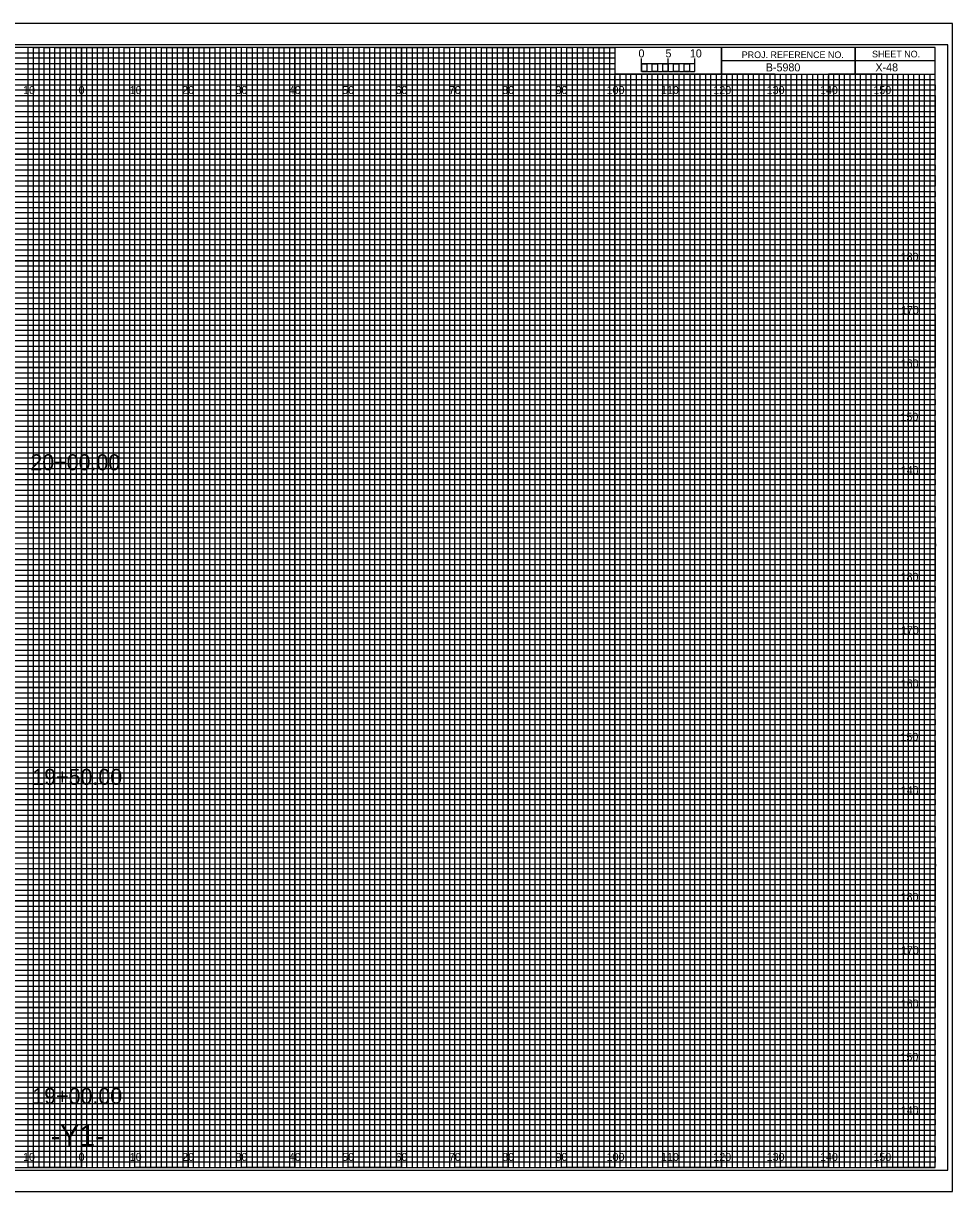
# Model space of a CAD drawing. Extents: x -13 to 323, y -5 to 4834.
# Drawn here: x 149.1 to 323.3, y 435.5 to 654.5 of the extents above; entities that cross this region are included whole.
import ezdxf

# ---------------------------------------------------------------- set-up
doc = ezdxf.new("R2010")
doc.units = 0
for name, color, linetype in [('Exist CMT Pavement', 7, 'Continuous'), ('Exist Cross Section Cell', 7, 'Continuous'), ('Exist XS Center Line Elevation Label', 7, 'Continuous'), ('Exist XS Ground Line', 7, 'Continuous'), ('Prop CMT Pvmt Course 1', 7, 'Continuous'), ('Prop CMT Pvmt Course 1 Wedge', 7, 'Continuous'), ('Prop CMT Pvmt Course 2', 7, 'Continuous'), ('Prop CMT Pvmt Course 2 Wedge', 7, 'Continuous'), ('Prop CMT Pvmt Course 3', 7, 'Continuous'), ('Prop CMT Pvmt Course 3 Wedge', 7, 'Continuous'), ('Prop CMT Pvmt Surface', 7, 'Continuous'), ('Prop CMT Pvmt Surface Shoulder', 7, 'Continuous'), ('Prop CMT Shld Paved Course 1', 7, 'Continuous'), ('Prop CMT Shld Paved Course 2', 7, 'Continuous'), ('Prop CMT Shld Paved Course 3', 7, 'Continuous'), ('Prop CMT Slope Grass', 7, 'Continuous'), ('Prop CMT Subgrade Earthwork', 7, 'Continuous')]:
    doc.layers.add(name, color=color, linetype=linetype)

msp = doc.modelspace()

# ---------------------------------------------------------------- linework, layer by layer
at = {"layer": 'Exist XS Center Line Elevation Label'}
for points in [[(145, 440), (155, 440), (155, 650), (165, 650), (165, 440), (175, 440), (175, 650), (185, 650), (185, 440), (195, 440), (195, 650), (205, 650), (205, 440), (215, 440), (215, 650), (225, 650), (225, 440), (235, 440), (235, 650), (245, 650), (245, 440), (255, 440), (255, 650), (259.93, 650), (260, 650), (260, 645), (264.99, 645), (264.99, 440), (275, 440), (275, 645), (285, 645), (285, 440), (295, 440), (295, 645), (305, 645), (305, 440), (315, 440), (315, 645)], [(0, 645), (275, 645)], [(0, 625), (320, 625), (320, 635), (0, 635)], [(0, 605), (320, 605), (320, 615), (0, 615)], [(0, 585), (320, 585), (320, 595), (0, 595)], [(0, 565), (320, 565), (320, 575), (0, 575)], [(0, 545), (320, 545), (320, 555), (0, 555)], [(0, 525), (320, 525), (320, 535), (0, 535)], [(0, 505), (320, 505), (320, 515), (0, 515)], [(0, 485), (320, 485), (320, 495), (0, 495)], [(0, 465), (320, 465), (320, 475), (0, 475)], [(0, 445), (320, 445), (320, 455), (0, 455)]]:
    msp.add_lwpolyline(points, dxfattribs=at)
at = {"layer": 'Exist XS Ground Line'}
for p, q in [((150, 650), (140, 650)), ((150, 440), (150, 650)), ((170, 650), (160, 650)), ((160, 650), (160, 440)), ((170, 440), (170, 650)), ((190, 650), (180, 650)), ((180, 650), (180, 440)), ((190, 440), (190, 650)), ((210, 650), (200, 650)), ((200, 650), (200, 440)), ((210, 440), (210, 650)), ((230, 650), (220, 650)), ((220, 650), (220, 440)), ((230, 440), (230, 650)), ((250, 650), (240, 650)), ((240, 650), (240, 440)), ((250, 440), (250, 650)), ((260, 650), (260, 440)), ((270, 440), (270, 645)), ((290, 645), (280, 645)), ((280, 645), (280, 440)), ((290, 440), (290, 645)), ((310, 645), (300, 645)), ((300, 645), (300, 440)), ((310, 440), (310, 645)), ((160, 440), (150, 440)), ((180, 440), (170, 440)), ((200, 440), (190, 440)), ((220, 440), (210, 440)), ((240, 440), (230, 440)), ((260, 440), (250, 440)), ((280, 440), (270, 440)), ((300, 440), (290, 440)), ((320, 440), (310, 440)), ((320, 440), (320, 440))]:
    msp.add_line(p, q, dxfattribs=at)
for points in [[(0, 640), (320, 640), (320, 630), (0, 630)], [(0, 620), (320, 620), (320, 610), (0, 610)], [(0, 600), (320, 600), (320, 590), (0, 590)], [(0, 580), (320, 580), (320, 570), (0, 570)], [(0, 560), (320, 560), (320, 550), (0, 550)], [(0, 540), (320, 540), (320, 530), (0, 530)], [(0, 520), (320, 520), (320, 510), (0, 510)], [(0, 500), (320, 500), (320, 490), (0, 490)], [(0, 480), (320, 480), (320, 470), (0, 470)], [(0, 460), (320, 460), (320, 450), (0, 450)]]:
    msp.add_lwpolyline(points, dxfattribs=at)
at = {"layer": 'Prop CMT Pvmt Course 1'}
for p, q in [((267, 645), (266.01, 645)), ((266.01, 645), (266.01, 440)), ((267, 440), (267, 645)), ((269, 645), (268, 645)), ((268, 645), (268, 440)), ((269, 440), (269, 645)), ((266.01, 440), (265, 440)), ((268, 440), (267, 440))]:
    msp.add_line(p, q, dxfattribs=at)
for points in [[(150, 440), (151, 440), (151, 650), (152, 650), (152, 440)], [(152, 440), (153, 440), (153, 650), (154, 650), (154, 440)], [(155, 440), (156, 440), (156, 650), (157, 650), (157, 440)], [(157, 440), (158, 440), (158, 650), (159, 650), (159, 440)], [(160, 440), (161, 440), (161, 650), (162, 650), (162, 440)], [(162, 440), (163, 440), (163, 650), (164, 650), (164, 440)], [(165, 440), (166, 440), (166, 650), (167, 650), (167, 440)], [(167, 440), (168, 440), (168, 650), (169, 650), (169, 440)], [(170, 440), (171, 440), (171, 650), (172, 650), (172, 440)], [(172, 440), (173, 440), (173, 650), (174, 650), (174, 440)], [(175, 440), (176, 440), (176, 650), (177, 650), (177, 440)], [(177, 440), (178, 440), (178, 650), (179, 650), (179, 440)], [(180, 440), (181, 440), (181, 650), (182, 650), (182, 440)], [(182, 440), (183, 440), (183, 650), (184, 650), (184, 440)], [(185, 440), (186, 440), (186, 650), (187, 650), (187, 440)], [(187, 440), (188, 440), (188, 650), (189, 650), (189, 440)], [(190, 440), (191, 440), (191, 650), (192, 650), (192, 440)], [(192, 440), (193, 440), (193, 650), (194, 650), (194, 440)], [(195, 440), (196, 440), (196, 650), (197, 650), (197, 440)], [(197, 440), (198, 440), (198, 650), (199, 650), (199, 440)], [(200, 440), (201, 440), (201, 650), (202, 650), (202, 440)], [(202, 440), (203, 440), (203, 650), (204, 650), (204, 440)], [(205, 440), (206, 440), (206, 650), (207, 650), (207, 440)], [(207, 440), (208, 440), (208, 650), (209, 650), (209, 440)], [(210, 440), (211, 440), (211, 650), (212, 650), (212, 440)], [(212, 440), (213, 440), (213, 650), (214, 650), (214, 440)], [(215, 440), (216, 440), (216, 650), (217, 650), (217, 440)], [(217, 440), (218, 440), (218, 650), (219, 650), (219, 440)], [(220, 440), (221, 440), (221, 650), (222, 650), (222, 440)], [(222, 440), (223, 440), (223, 650), (224, 650), (224, 440)], [(225, 440), (226, 440), (226, 650), (227, 650), (227, 440)], [(227, 440), (228, 440), (228, 650), (229, 650), (229, 440)], [(230, 440), (231, 440), (231, 650), (232, 650), (232, 440)], [(232, 440), (233, 440), (233, 650), (234, 650), (234, 440)], [(235, 440), (236, 440), (236, 650), (237, 650), (237, 440)], [(237, 440), (238, 440), (238, 650), (239, 650), (239, 440)], [(240, 440), (241, 440), (241, 650), (242, 650), (242, 440)], [(242, 440), (243, 440), (243, 650), (244, 650), (244, 440)], [(245, 440), (246, 440), (246, 650), (247, 650), (247, 440)], [(247, 440), (248, 440), (248, 650), (249, 650), (249, 440)], [(250, 440), (251, 440), (251, 650), (252, 650), (252, 440)], [(252, 440), (253, 440), (253, 650), (254, 650), (254, 440)], [(255, 440), (256, 440), (256, 650), (257, 650), (257, 440)], [(257, 440), (258, 440), (258, 650), (259, 650), (259, 440)], [(260, 440), (261, 440), (261, 645), (262.02, 645), (262.02, 440)], [(262, 440), (263, 440), (263, 645), (263.99, 645), (263.99, 440)], [(270, 440), (270.98, 440), (270.98, 645), (272, 645), (272, 440)], [(272, 440), (273, 440), (273, 645), (274.05, 645), (274.05, 440)], [(275, 440), (276, 440), (276, 645), (277, 645), (277, 440)], [(277, 440), (278, 440), (278, 645), (279, 645), (279, 440)], [(280, 440), (281, 440), (281, 645), (282, 645), (282, 440)], [(282, 440), (283, 440), (283, 645), (284, 645), (284, 440)], [(285, 440), (286, 440), (286, 645), (287, 645), (287, 440)], [(287, 440), (288, 440), (288, 645), (289, 645), (289, 440)], [(290, 440), (291, 440), (291, 645), (292, 645), (292, 440)], [(292, 440), (293, 440), (293, 645), (294, 645), (294, 440)], [(295, 440), (296, 440), (296, 645), (297, 645), (297, 440)], [(297, 440), (298, 440), (298, 645), (299, 645), (299, 440)], [(300, 440), (301, 440), (301, 645), (302, 645), (302, 440)], [(302, 440), (303, 440), (303, 645), (304, 645), (304, 440)], [(305, 440), (306, 440), (306, 645), (307, 645), (307, 440)], [(307, 440), (308, 440), (308, 645), (309, 645), (309, 440)], [(310, 440), (311, 440), (311, 645), (312, 645), (312, 440)], [(312, 440), (313, 440), (313, 645), (314, 645), (314, 440)], [(315, 440), (316, 440), (316, 645), (317, 645), (317, 440)], [(317, 440), (318, 440), (318, 645), (319, 645), (319, 440)]]:
    msp.add_lwpolyline(points, dxfattribs=at)
at = {"layer": 'Prop CMT Pvmt Course 2'}
for p, q in [((323.3, 654.5), (-13.4, 654.5)), ((-13.4, 435.5), (323.3, 435.5))]:
    msp.add_line(p, q, dxfattribs=at)
at = {"layer": 'Prop CMT Pvmt Surface Shoulder'}
for p, q in [((305, 650), (305, 645)), ((305, 645), (305, 650)), ((280, 647.5), (280, 645)), ((320, 647.49), (280, 647.49)), ((280, 645), (320, 645))]:
    msp.add_line(p, q, dxfattribs=at)
for points in [[(320, 650), (0, 650), (0, 440), (320, 440)], [(280, 650), (260, 650), (260, 645.03), (280, 645.03)], [(320, 650), (280, 650), (280, 645), (320, 645)]]:
    msp.add_lwpolyline(points, close=True, dxfattribs=at)
at = {"layer": 'Prop CMT Shld Paved Course 1'}
msp.add_lwpolyline([(-13.4, 435.5), (323.3, 435.5), (323.3, 654.5), (-13.4, 654.5)], close=True, dxfattribs=at)
at = {"layer": 'Prop CMT Shld Paved Course 2'}
msp.add_lwpolyline([(-10.8, 439.5), (322.4, 439.5), (322.4, 650.5), (-10.8, 650.5)], close=True, dxfattribs=at)
at = {"layer": 'Prop CMT Shld Paved Course 3'}
for p, q in [((150, 440), (150, 650)), ((160, 440), (160, 650)), ((170, 440), (170, 650)), ((180, 440), (180, 650)), ((190, 440), (190, 650)), ((200, 440), (200, 650)), ((210, 440), (210, 650)), ((220, 440), (220, 650)), ((230, 440), (230, 650)), ((240, 440), (240, 650)), ((250, 440), (250, 650)), ((260, 440), (260, 644.69)), ((270, 440), (270, 644.69)), ((280, 440), (280, 644.69)), ((290, 440), (290, 644.69)), ((300, 440), (300, 644.69)), ((310, 440), (310, 644.69)), ((0, 640), (320, 640)), ((0, 630), (320, 630)), ((0, 620), (320, 620)), ((0, 610), (320, 610)), ((0, 600), (320, 600)), ((0, 590), (320, 590)), ((0, 580), (320, 580)), ((0, 570), (320, 570)), ((0, 560), (320, 560)), ((0, 550), (320, 550)), ((0, 540), (320, 540)), ((0, 530), (320, 530)), ((0, 520), (320, 520)), ((0, 510), (320, 510)), ((0, 500), (320, 500)), ((0, 490), (320, 490)), ((0, 480), (320, 480)), ((0, 470), (320, 470)), ((0, 460), (320, 460)), ((0, 450), (320, 450))]:
    msp.add_line(p, q, dxfattribs=at)
at = {"layer": 'Prop CMT Slope Grass'}
for p, q in [((0, 649), (260, 649)), ((260, 649), (260, 647.98)), ((260, 647.98), (0, 647.98)), ((0, 647), (260, 647)), ((260, 647), (260, 645.89)), ((260, 645.89), (0, 645.89)), ((0, 644), (320, 644))]:
    msp.add_line(p, q, dxfattribs=at)
for points in [[(0, 643), (270, 643), (320, 643), (320, 642), (0, 642)], [(0, 641), (320, 641), (320, 639), (0, 639)], [(0, 638), (320, 638), (320, 637), (0, 636.98)], [(0, 636), (320, 636), (320, 634), (0, 634)], [(0, 633), (320, 633), (320, 632), (0, 632)], [(0, 631), (320, 631), (320, 629), (0, 629)], [(0, 628), (320, 628), (320, 627), (0, 627)], [(0, 626), (320, 626), (320, 624), (0, 624)], [(0, 623), (320, 623), (320, 622), (0, 622)], [(0, 621), (320, 621), (320, 619), (0, 619)], [(0, 618), (320, 618), (320, 617), (0, 617)], [(0, 616), (320, 616), (320, 613.95), (320, 613), (320, 612), (0, 612)], [(0, 614), (320, 614), (320, 613), (0, 613)], [(0, 611), (320, 611), (320, 609), (0, 609.03)], [(0, 609.03), (320, 609), (320, 608), (0, 608)], [(0, 607), (320, 607), (320, 606), (0, 606)], [(0, 604), (320, 604), (320, 603), (0, 603)], [(0, 602), (320, 602), (320, 601), (0, 601)], [(-0.07, 598.89), (320, 598.89), (320, 597.88), (-0.07, 597.88)], [(0, 597), (320, 597), (320, 596), (0, 596)], [(0, 594), (320, 594), (320, 593), (0, 593)], [(0, 592), (320, 592), (320, 591), (0, 591)], [(0, 589), (320, 589), (320, 588), (0, 588)], [(0, 587), (320, 587), (320, 586), (0, 586)], [(0, 584), (320, 584), (320, 583), (0, 583)], [(0, 582), (320, 582), (320, 581), (0, 581)], [(0, 579), (320, 579), (319.99, 577.98), (0, 578)], [(0, 577), (320, 577), (320, 576), (0, 576)], [(0, 574), (320, 574), (320, 573), (0, 573)], [(0, 572), (320, 572), (320, 571), (0, 571)], [(0, 569), (320, 569), (320, 568), (0, 568)], [(0, 567), (320, 567), (320, 566), (0, 566)], [(0, 564), (320, 564), (320, 563), (0, 563)], [(0, 562), (320, 562), (320, 561), (0, 561)], [(0, 559), (320, 559), (320, 558), (0, 558)], [(0, 556.99), (320.07, 556.91), (320, 556), (0, 556)], [(0, 554), (320, 554), (320, 553), (0, 553)], [(0, 552), (320, 552), (320, 551), (0, 551)], [(0, 549), (320, 549), (320, 548), (0, 548)], [(0, 547), (320, 547), (320, 546), (0, 546)], [(0, 544), (320, 544), (320, 543), (0, 543)], [(0, 542), (320, 542), (320, 541), (0, 541)], [(0, 539), (320, 539), (320, 538), (0, 538)], [(0, 537), (320, 537), (320, 536), (0, 536)], [(0, 534), (320, 534), (320, 533), (0, 533)], [(0, 532), (320, 532), (320, 531), (0, 531)], [(0, 529), (320, 529), (320, 528), (0, 528)], [(0, 527), (320, 527), (320, 526), (0, 526)], [(0, 524), (320, 524), (320, 523), (0, 523)], [(0, 522), (320, 522), (320, 521), (0, 521)], [(0, 519), (320, 519), (319.99, 517.98), (0, 518)], [(0, 517), (320, 517), (320, 516), (0, 516)], [(0, 514), (320, 514), (320, 513), (0, 513)], [(0, 512), (320, 512), (320, 511), (0, 511)], [(0, 509), (320, 509), (320, 508), (0, 508)], [(0, 507), (320, 507), (320, 506), (0, 506)], [(0, 504), (320, 504), (320, 503), (0, 503)], [(0, 502), (320, 502), (320, 501), (0, 501)], [(0, 499), (320, 499), (320, 498), (0, 498)], [(0, 496.99), (320.07, 496.91), (320, 496), (0, 496)], [(0, 494), (320, 494), (320, 493), (0, 493)], [(0, 492), (320, 492), (320, 491), (0, 491)], [(0, 489), (320, 489), (320, 488), (0, 488)], [(0, 487), (320, 487), (320, 486), (0, 486)], [(0, 484), (320, 484), (320, 483), (0, 483)], [(0, 482), (320, 482), (320, 481), (0, 481)], [(0, 479), (320, 479), (320, 478), (0, 478)], [(0, 477), (320, 477), (320, 476), (0, 476)], [(0, 474), (320, 474), (320, 473), (0, 473)], [(0, 472), (320, 472), (320, 471), (0, 471)], [(0, 469), (320, 469), (320, 468), (0, 468)], [(0, 467), (320, 467), (320, 466), (0, 466)], [(0, 464), (320, 464), (320, 463), (0, 463)], [(0, 462), (320, 462), (320, 461), (0, 461)], [(0, 459), (320, 459), (320, 458), (0, 458)], [(0, 457), (320, 457), (320, 456), (0, 456)], [(0, 454), (320, 454), (320, 453), (0, 453)], [(0, 452), (320, 452), (320, 451), (0, 451)], [(0, 449), (320, 449), (320, 448), (0, 448)], [(0, 447), (320, 447), (320, 446), (0, 446)], [(0, 444), (320, 444), (320, 443), (0, 443)], [(0, 442), (320, 442), (320, 441), (0, 441)]]:
    msp.add_lwpolyline(points, dxfattribs=at)
at = {"layer": 'Prop CMT Subgrade Earthwork'}
for p, q in [((265, 645.49), (265, 647.9)), ((265, 646.9), (265, 647.9)), ((270, 645.49), (270, 647.9)), ((275, 645.49), (275, 647.9)), ((275, 646.9), (275, 647.9))]:
    msp.add_line(p, q, dxfattribs=at)
for points in [[(275, 646.9), (265, 646.9), (265, 645.49), (275, 645.49)], [(265, 646.9), (266, 646.9), (266, 645.49), (265, 645.49)], [(267, 646.9), (268, 646.9), (268, 645.49), (267, 645.49)], [(269, 646.9), (270, 646.9), (270, 645.49), (269, 645.49)], [(271, 646.9), (272, 646.9), (272, 645.49), (271, 645.49)], [(273, 646.9), (274, 646.9), (274, 645.49), (273, 645.49)]]:
    msp.add_lwpolyline(points, close=True, dxfattribs=at)

# ---------------------------------------------------------------- texts
at = {"layer": 'Exist CMT Pavement'}
msp.add_text('-Y1-', height=4, dxfattribs=at).set_placement((154.21, 444))
at = {"layer": 'Exist Cross Section Cell'}
for s, p in [('10', (149.04, 641.25)), ('0', (159.45, 641.25)), ('0', (159.45, 641.25)), ('10', (169.04, 641.25)), ('20', (178.86, 641.25)), ('30', (188.86, 641.25)), ('40', (198.86, 641.25)), ('50', (208.86, 641.25)), ('60', (218.86, 641.25)), ('70', (228.86, 641.25)), ('80', (238.86, 641.25)), ('90', (248.86, 641.25)), ('100', (258.44, 641.25)), ('110', (268.62, 641.25)), ('120', (278.44, 641.25)), ('130', (288.44, 641.25)), ('140', (298.44, 641.25)), ('150', (308.44, 641.25)), ('10', (149.04, 441.25)), ('0', (159.45, 441.25)), ('0', (159.45, 441.25)), ('10', (169.04, 441.25)), ('20', (178.86, 441.25)), ('30', (188.86, 441.25)), ('40', (198.86, 441.25)), ('50', (208.86, 441.25)), ('60', (218.86, 441.25)), ('70', (228.86, 441.25)), ('80', (238.86, 441.25)), ('90', (248.86, 441.25)), ('100', (258.44, 441.25)), ('110', (268.62, 441.25)), ('120', (278.44, 441.25)), ('130', (288.44, 441.25)), ('140', (298.44, 441.25)), ('150', (308.44, 441.25))]:
    msp.add_text(s, height=1.5, dxfattribs=at).set_placement(p)
at = {"layer": 'Prop CMT Pvmt Course 1 Wedge'}
for s, p in [('20+00.00', (150.41, 570.72)), ('19+50.00', (150.77, 511.75)), ('19+00.00', (150.77, 451.94))]:
    msp.add_text(s, height=3, dxfattribs=at).set_placement(p)
at = {"layer": 'Prop CMT Pvmt Course 2 Wedge'}
msp.add_text('X-48', height=1.5, dxfattribs=at).set_placement((308.83, 645.5))
at = {"layer": 'Prop CMT Pvmt Course 3'}
for s, p in [('180', (313.55, 610)), ('170', (313.61, 600)), ('160', (313.57, 590)), ('150', (313.52, 580)), ('140', (313.57, 570)), ('180', (313.55, 550)), ('170', (313.61, 540)), ('160', (313.57, 530)), ('150', (313.52, 520)), ('140', (313.57, 510)), ('180', (313.55, 490)), ('170', (313.61, 480)), ('160', (313.57, 470)), ('150', (313.52, 460)), ('140', (313.57, 450))]:
    msp.add_text(s, height=1.5, dxfattribs=at).set_placement(p)
at = {"layer": 'Prop CMT Pvmt Course 3 Wedge'}
msp.add_text('B-5980', height=1.5, dxfattribs=at).set_placement((288.28, 645.5))
at = {"layer": 'Prop CMT Pvmt Surface'}
for s, p in [('5', (269.47, 648.12)), ('10', (274.04, 648.12))]:
    msp.add_text(s, height=1.5, dxfattribs=at).set_placement(p)
at = {"layer": 'Prop CMT Pvmt Surface Shoulder'}
for s, p in [('PROJ. REFERENCE NO.', (283.77, 647.99)), ('SHEET NO.', (308.19, 648.12))]:
    msp.add_text(s, height=1.25, dxfattribs=at).set_placement(p)
at = {"layer": 'Prop CMT Subgrade Earthwork'}
msp.add_text('0', height=1.5, dxfattribs=at).set_placement((264.41, 648.12))

doc.saveas('drawing.dxf')
